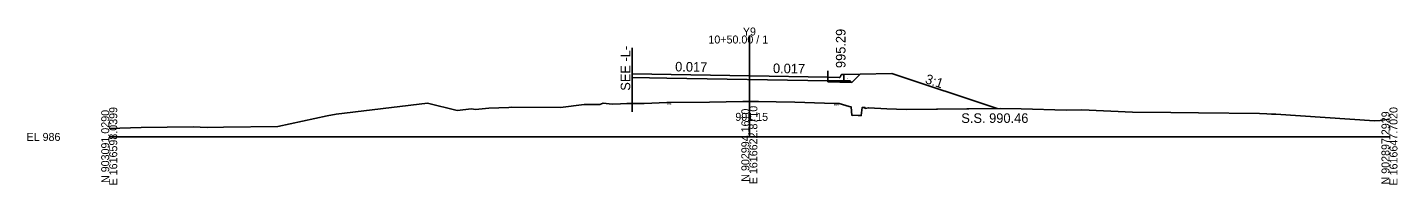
# Model space of a CAD drawing. Extents: x -26 to 1403, y -10 to 3021.
# Drawn here: x -12.8 to 201.3, y 492.5 to 517.1 of the extents above; entities that cross this region are included whole.
import ezdxf

# ---------------------------------------------------------------- set-up
doc = ezdxf.new("R2010")
doc.units = 0
for name, color, linetype in [('Exist Cross Section Cell', 7, 'Continuous'), ('Exist XS Center Line Elevation Label', 7, 'Continuous'), ('Exist XS Ground Line', 7, 'Continuous'), ('Prop XS Dump Level', 7, 'Continuous'), ('Prop XS Earthwork Shape', 7, 'Continuous'), ('Prop XS EOT Tick Mark', 7, 'Continuous'), ('Prop XS Finish Grade', 7, 'Continuous'), ('Prop XS Finish Grade CurbGutter', 7, 'Continuous'), ('Prop XS Finish Grade Earthwork', 7, 'Continuous'), ('Prop XS Finish Grade Pavement', 7, 'Continuous'), ('Prop XS Hydro Elevations', 7, 'Continuous'), ('Prop XS Pvmt Edge Slope', 7, 'Continuous'), ('Prop XS SE Text', 7, 'Continuous'), ('Prop XS Side Slope Text', 7, 'Continuous'), ('Prop XS SS Elevation Text', 7, 'Continuous'), ('Prop XS Subgrade CurbGutter', 7, 'Continuous'), ('Prop XS Subgrade Earthwork', 7, 'Continuous')]:
    doc.layers.add(name, color=color, linetype=linetype)

msp = doc.modelspace()

# ---------------------------------------------------------------- linework, layer by layer
at = {"layer": 'Exist Cross Section Cell'}
for p, q in [((100, 500), (100, 515.87)), ((0, 500), (100, 500)), ((100, 500), (200, 500))]:
    msp.add_line(p, q, dxfattribs=at)
at = {"layer": 'Exist XS Ground Line'}
for p, q in [((35.47, 503.58), (49.73, 505.29)), ((49.73, 505.29), (54.33, 504.16)), ((76.62, 505.09), (77.16, 505.28)), ((77.16, 505.28), (78.58, 505.11)), ((78.58, 505.11), (79.86, 505.17)), ((79.86, 505.17), (80.84, 505.24)), ((80.84, 505.24), (83.57, 505.24)), ((83.57, 505.24), (87.12, 505.41)), ((87.12, 505.41), (87.72, 505.38)), ((87.72, 505.38), (93.78, 505.43)), ((93.78, 505.43), (98.99, 505.55)), ((98.99, 505.55), (100, 505.56)), ((100, 505.56), (101.41, 505.57)), ((101.41, 505.57), (104.19, 505.48)), ((104.19, 505.48), (107.1, 505.42)), ((107.1, 505.42), (111.73, 505.28)), ((111.73, 505.28), (113.24, 505.21)), ((113.24, 505.21), (113.4, 505.22)), ((113.4, 505.22), (114.05, 505.23)), ((114.05, 505.23), (115.58, 504.78)), ((26.35, 501.64), (34.05, 503.28)), ((34.05, 503.28), (35.47, 503.58)), ((54.33, 504.16), (56.59, 504.39)), ((56.59, 504.39), (57.21, 504.32)), ((57.21, 504.32), (59.28, 504.49)), ((59.28, 504.49), (62.44, 504.62)), ((62.44, 504.62), (62.78, 504.64)), ((62.78, 504.64), (70.5, 504.61)), ((70.5, 504.61), (74.2, 505.08)), ((74.2, 505.08), (76.62, 505.09)), ((115.58, 504.78), (115.91, 504.7)), ((115.91, 504.7), (116.01, 503.37)), ((116.01, 503.37), (116.13, 503.39)), ((116.13, 503.39), (116.99, 503.38)), ((116.99, 503.38), (117.37, 503.37)), ((117.37, 503.37), (117.48, 503.35)), ((117.48, 503.35), (117.64, 504.63)), ((117.64, 504.63), (118.06, 504.62)), ((118.06, 504.62), (118.09, 504.47)), ((118.09, 504.47), (118.61, 504.58)), ((118.61, 504.58), (121.48, 504.38)), ((121.48, 504.38), (124.5, 504.32)), ((124.5, 504.32), (139.18, 504.46)), ((139.18, 504.46), (142.44, 504.38)), ((142.44, 504.38), (149.51, 504.21)), ((149.51, 504.21), (151.94, 504.23)), ((151.94, 504.23), (159.83, 503.88)), ((159.83, 503.88), (165.82, 503.82)), ((165.82, 503.82), (170.15, 503.76)), ((170.15, 503.76), (179.7, 503.65)), ((179.7, 503.65), (180.84, 503.61)), ((180.84, 503.61), (181.59, 503.58)), ((181.59, 503.58), (182.23, 503.54)), ((182.23, 503.54), (197.68, 502.54)), ((0, 501.33), (4.97, 501.48)), ((4.97, 501.48), (13.12, 501.57)), ((13.12, 501.57), (15.3, 501.48)), ((15.3, 501.48), (17.87, 501.53)), ((17.87, 501.53), (26.35, 501.64)), ((197.68, 502.54), (198.56, 502.59)), ((198.56, 502.59), (200, 502.76))]:
    msp.add_line(p, q, dxfattribs=at)
at = {"layer": 'Prop XS Dump Level'}
for p, q in [((100, 509.56), (81.7, 509.87)), ((112.27, 509.36), (100, 509.56))]:
    msp.add_line(p, q, dxfattribs=at)
at = {"layer": 'Prop XS Earthwork Shape'}
msp.add_lwpolyline([(112.27, 508.6), (116.02, 508.54), (117.32, 509.84), (122.27, 509.94), (138.72, 504.46), (124.5, 504.32), (121.48, 504.38), (118.61, 504.58), (118.09, 504.47), (118.06, 504.62), (117.64, 504.63), (117.48, 503.35), (117.37, 503.37), (116.99, 503.38), (116.13, 503.39), (116.01, 503.37), (115.91, 504.7), (115.58, 504.78), (114.05, 505.23), (113.4, 505.22), (113.24, 505.21), (111.73, 505.28), (107.1, 505.42), (104.19, 505.48), (101.41, 505.57), (100, 505.56), (98.99, 505.55), (93.78, 505.43), (87.72, 505.38), (87.12, 505.41), (83.57, 505.24), (81.7, 505.24), (81.7, 509.28), (87.12, 509.19), (112.27, 508.77)], close=True, dxfattribs=at)
at = {"layer": 'Prop XS EOT Tick Mark'}
for p, q in [((81.7, 503.95), (81.7, 513.92)), ((112.27, 509.36), (112.27, 510.36))]:
    msp.add_line(p, q, dxfattribs=at)
at = {"layer": 'Prop XS Finish Grade'}
msp.add_line((114.77, 509.78), (117.32, 509.84), dxfattribs=at)
at = {"layer": 'Prop XS Finish Grade CurbGutter'}
for p, q in [((114.23, 509.41), (114.3, 509.66)), ((114.3, 509.66), (114.39, 509.75)), ((114.52, 509.78), (114.39, 509.75)), ((114.77, 509.78), (114.52, 509.78)), ((112.27, 509.36), (114.02, 509.29)), ((114.02, 509.29), (114.14, 509.32)), ((114.14, 509.32), (114.23, 509.41))]:
    msp.add_line(p, q, dxfattribs=at)
at = {"layer": 'Prop XS Finish Grade Earthwork'}
for p, q in [((117.32, 509.84), (122.27, 509.94)), ((122.27, 509.94), (138.72, 504.46))]:
    msp.add_line(p, q, dxfattribs=at)
at = {"layer": 'Prop XS Finish Grade Pavement'}
for p, q in [((81.7, 509.87), (100, 509.56)), ((100, 509.56), (112.27, 509.36))]:
    msp.add_line(p, q, dxfattribs=at)
at = {"layer": 'Prop XS Pvmt Edge Slope'}
for p, q in [((114.77, 508.79), (115.77, 508.79)), ((115.77, 508.79), (116.02, 508.54))]:
    msp.add_line(p, q, dxfattribs=at)
at = {"layer": 'Prop XS Subgrade CurbGutter'}
for p, q in [((114.77, 508.79), (114.77, 509.78)), ((112.27, 509.36), (112.27, 508.78)), ((112.27, 508.78), (114.77, 508.79))]:
    msp.add_line(p, q, dxfattribs=at)
at = {"layer": 'Prop XS Subgrade Earthwork'}
for p, q in [((116.02, 508.54), (117.32, 509.84)), ((81.7, 509.28), (81.7, 505.24)), ((87.12, 509.19), (81.7, 509.28)), ((87.12, 509.19), (112.27, 508.77)), ((112.27, 508.6), (112.27, 508.77)), ((112.27, 508.6), (116.02, 508.54))]:
    msp.add_line(p, q, dxfattribs=at)

# ---------------------------------------------------------------- texts
at = {"layer": 'Exist Cross Section Cell'}
for s, p in [('10+50.00 / 1', (93.6, 514.62)), ('Y9', (98.98, 515.87)), ('EL 986', (-12.92, 499.38))]:
    msp.add_text(s, height=1.25, dxfattribs=at).set_placement(p)
for s, p in [('N 903091.0290', (0, 492.8)), ('E 1616598.0399', (1.25, 492.42)), ('N 902994.1610', (100, 493)), ('E 1616622.8710', (101.25, 492.61)), ('N 902897.2929', (200, 492.57)), ('E 1616647.7020', (201.25, 492.41))]:
    msp.add_text(s, height=1.25, rotation=90, dxfattribs=at).set_placement(p)
at = {"layer": 'Exist XS Center Line Elevation Label'}
msp.add_text('991.15', height=1.25, dxfattribs=at).set_placement((97.81, 502.52))
at = {"layer": 'Prop XS Dump Level'}
for s, height, p in [('Case1', 0.04, (115.27, 509.09)), ('Eop', 0.3, (87.12, 505.11)), ('Eop', 0.3, (113.24, 504.91))]:
    msp.add_text(s, height=height, dxfattribs=at).set_placement(p)
at = {"layer": 'Prop XS Hydro Elevations'}
msp.add_text('995.29', height=1.5, rotation=90, dxfattribs=at).set_placement((115.02, 510.78))
at = {"layer": 'Prop XS SE Text'}
for s, rotation, p in [('SEE -L-', 90, (81.4, 507.23)), ('0.017', 359.0429, (88.4, 510.26)), ('0.017', 359.0429, (103.68, 510))]:
    msp.add_text(s, height=1.5, rotation=rotation, dxfattribs=at).set_placement(p)
at = {"layer": 'Prop XS Side Slope Text'}
msp.add_text('3:1', height=1.5, rotation=341.5651, dxfattribs=at).set_placement((127.35, 508.46))
at = {"layer": 'Prop XS SS Elevation Text'}
msp.add_text('S.S. 990.46', height=1.5, dxfattribs=at).set_placement((133.11, 502.2))

doc.saveas('drawing.dxf')
